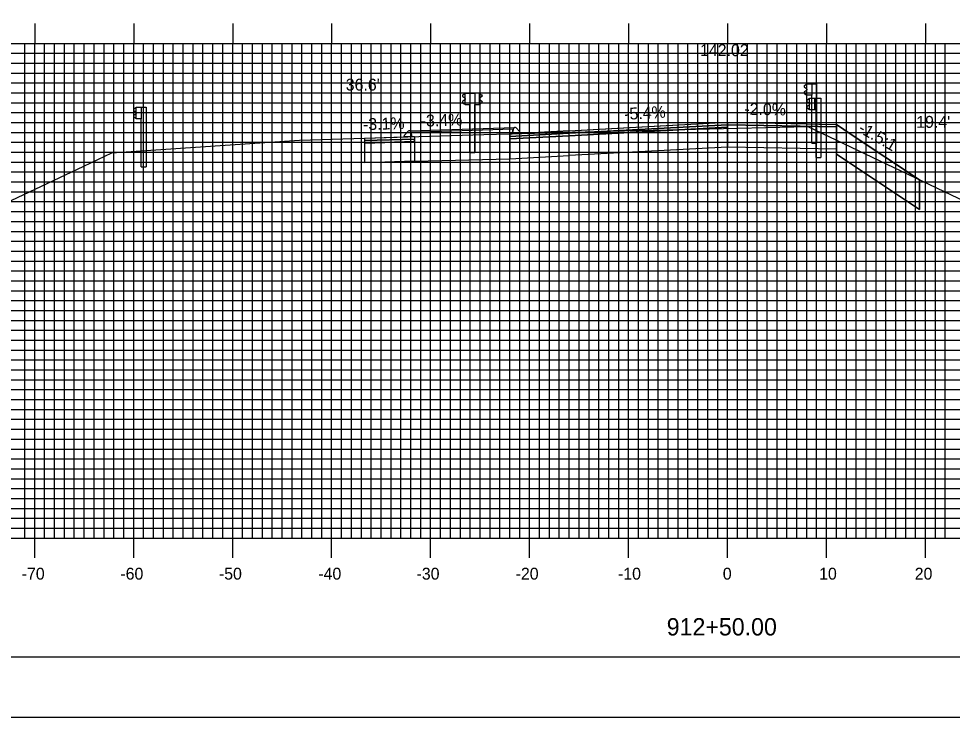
# Model space of a CAD drawing. Extents: x 860258 to 860601, y 364765 to 364985.
# Drawn here: x 860352.3 to 860446.6, y 364765.2 to 364835.8 of the extents above; entities that cross this region are included whole.
import ezdxf

# ---------------------------------------------------------------- set-up
doc = ezdxf.new("R2010")
doc.units = 0
for name, color, linetype in [('ANNOTATION', 7, 'Continuous'), ('BORDER', 7, 'Continuous'), ('D_Curb_Type_3M2_Lt', 7, 'Continuous'), ('D_Curb_Type_3M2_Rt', 7, 'Continuous'), ('D_Guardrail_Beam_Rt', 7, 'Continuous'), ('D_Roadway_Centerline', 7, 'Continuous'), ('D_Roadway_Centerline_Text', 7, 'Continuous'), ('D_Roadway_Edge_Shoulder', 7, 'Continuous'), ('D_Roadway_Edge_TW', 7, 'Continuous'), ('D_Roadway_FinishedGrade', 7, 'Continuous'), ('D_Roadway_Pavement', 7, 'Continuous'), ('D_Roadway_SubGrade', 7, 'Continuous'), ('D_Text_Standard', 7, 'Continuous'), ('H_V ANNOTATION', 7, 'Continuous'), ('M_Guardrail', 7, 'Continuous'), ('M_Roadway_Centerline', 7, 'Continuous'), ('MAJOR', 7, 'Continuous'), ('MINOR', 7, 'Continuous'), ('PATTERNING', 7, 'Continuous'), ('PLOT BOUNDARY', 7, 'Continuous'), ('S_Roadway_Centerline', 7, 'Continuous')]:
    doc.layers.add(name, color=color, linetype=linetype)

msp = doc.modelspace()

# ---------------------------------------------------------------- linework, layer by layer
at = {"layer": 'BORDER'}
msp.add_lwpolyline([(860274.299, 364771.302), (860594.299, 364771.302), (860594.299, 364981.302), (860274.299, 364981.302)], close=True, dxfattribs=at)
at = {"layer": 'D_Curb_Type_3M2_Lt'}
for p, q in [((860402.257, 364824.685), (860402.149, 364824.191)), ((860402.149, 364824.191), (860402.899, 364824.191)), ((860402.393, 364824.814), (860402.398, 364824.814)), ((860402.899, 364824.358), (860402.545, 364824.76)), ((860402.899, 364824.191), (860402.899, 364824.358))]:
    msp.add_line(p, q, dxfattribs=at)
msp.add_arc((860402.42, 364824.65), 0.167, 41.38705, 167.66476, dxfattribs=at)
at = {"layer": 'D_Curb_Type_3M2_Rt'}
for p, q in [((860391.259, 364824.017), (860391.613, 364824.419)), ((860391.901, 364824.344), (860392.009, 364823.85)), ((860391.259, 364823.85), (860391.259, 364824.017)), ((860392.009, 364823.85), (860391.259, 364823.85))]:
    msp.add_line(p, q, dxfattribs=at)
msp.add_arc((860391.738, 364824.309), 0.167, 12.33524, 138.61295, dxfattribs=at)
at = {"layer": 'D_Guardrail_Beam_Rt'}
for p, q in [((860432.08, 364827.644), (860431.937, 364827.544)), ((860431.937, 364827.401), (860432.132, 364827.265)), ((860432.132, 364827.066), (860431.937, 364826.93)), ((860432.17, 364827.665), (860432.096, 364827.651)), ((860432.166, 364827.2), (860432.166, 364827.13)), ((860432.17, 364827.749), (860432.858, 364827.749)), ((860432.17, 364826.582), (860432.17, 364827.749)), ((860432.691, 364827.749), (860432.691, 364826.582)), ((860432.795, 364827.749), (860432.795, 364826.582)), ((860432.858, 364827.749), (860433.329, 364827.749)), ((860432.858, 364827.749), (860432.858, 364826.582)), ((860433.329, 364827.749), (860433.329, 364821.749)), ((860431.937, 364826.786), (860432.08, 364826.686)), ((860432.096, 364826.68), (860432.17, 364826.665)), ((860432.858, 364826.582), (860432.17, 364826.582)), ((860432.837, 364821.749), (860432.837, 364826.582)), ((860432.837, 364821.749), (860433.329, 364821.749))]:
    msp.add_line(p, q, dxfattribs=at)
for centre, major_axis, start_param, end_param in [((860431.987, 364827.472), (-0.0877, 0), 5.323254, 7.243116), ((860431.987, 364826.858), (-0.0877, 0), 5.323254, 7.243116), ((860432.104, 364827.61), (-0.0417, 0), 4.907132, 5.323254), ((860432.087, 364827.2), (0.0789, 0), 0, 0.959931), ((860432.087, 364827.13), (0.0789, 0), 5.323254, 6.283185), ((860432.104, 364826.72), (-0.0417, 0), 0.959931, 1.376053)]:
    msp.add_ellipse(centre, major_axis=major_axis, ratio=0.995501, start_param=start_param, end_param=end_param, dxfattribs=at)
at = {"layer": 'D_Roadway_Centerline'}
for points in [[(860402.899, 364824.191), (860407.899, 364824.461), (860413.37, 364824.757), (860423.9, 364825.325), (860423.903, 364825.325), (860429.097, 364825.221), (860431.9, 364825.165), (860433.135, 364825.141), (860434.899, 364825.105), (860443.295, 364819.508)], [(860387.259, 364823.725), (860387.283, 364823.725), (860391.139, 364823.846), (860391.259, 364823.85)]]:
    msp.add_lwpolyline(points, dxfattribs=at)
at = {"layer": 'D_Roadway_Edge_Shoulder'}
for points in [[(860423.9, 364825.325), (860431.899, 364825.165), (860431.899, 364825.165), (860434.899, 364825.105), (860434.899, 364824.855), (860423.9, 364825.075)], [(860407.899, 364824.461), (860402.899, 364824.191), (860401.9, 364824.137), (860401.9, 364823.887), (860407.899, 364824.211)], [(860387.259, 364823.725), (860391.259, 364823.85), (860392.259, 364823.881), (860392.259, 364823.631), (860387.259, 364823.475)]]:
    msp.add_lwpolyline(points, close=True, dxfattribs=at)
at = {"layer": 'D_Roadway_Edge_TW'}
msp.add_lwpolyline([(860407.899, 364824.461), (860423.9, 364825.325), (860423.9, 364825.075), (860407.899, 364824.211)], close=True, dxfattribs=at)
at = {"layer": 'D_Roadway_FinishedGrade'}
msp.add_line((860434.899, 364825.105), (860434.899, 364822.105), dxfattribs=at)
for points in [[(860434.899, 364825.105), (860436.399, 364824.105), (860443.295, 364819.508)], [(860391.78, 364824.47), (860402.378, 364824.811)], [(860443.295, 364819.508), (860443.295, 364816.508), (860434.899, 364822.105)]]:
    msp.add_lwpolyline(points, dxfattribs=at)
at = {"layer": 'D_Roadway_Pavement'}
for points in [[(860407.899, 364824.211), (860423.9, 364825.075), (860423.9, 364824.825), (860407.899, 364823.961)], [(860407.899, 364824.211), (860401.9, 364823.887), (860401.9, 364823.637), (860407.899, 364823.961)], [(860387.259, 364823.475), (860392.259, 364823.631), (860392.259, 364823.381), (860387.259, 364823.225)]]:
    msp.add_lwpolyline(points, close=True, dxfattribs=at)
msp.add_lwpolyline([(860423.9, 364825.075), (860423.9, 364824.825)], dxfattribs=at)
msp.add_lwpolyline([(860423.9, 364825.075), (860423.9, 364824.825)], dxfattribs=at)
at = {"layer": 'D_Roadway_SubGrade'}
for points in [[(860423.9, 364824.825), (860423.9, 364825.075), (860434.899, 364824.855), (860434.899, 364825.105), (860434.899, 364822.605), (860423.9, 364822.825)], [(860392.259, 364823.881), (860392.259, 364821.381), (860401.9, 364821.637), (860401.9, 364823.637), (860401.9, 364823.887), (860401.9, 364824.137), (860402.14, 364824.15), (860402.247, 364824.64), (860391.909, 364824.307), (860392.004, 364823.874)], [(860407.899, 364823.961), (860423.9, 364824.825), (860423.9, 364822.825), (860407.899, 364821.961)], [(860387.259, 364823.225), (860392.259, 364823.381), (860392.259, 364823.631), (860392.259, 364821.381), (860387.259, 364821.225)], [(860407.899, 364823.961), (860401.9, 364823.637), (860401.9, 364823.887), (860401.9, 364821.637), (860407.899, 364821.961)]]:
    msp.add_lwpolyline(points, close=True, dxfattribs=at)
at = {"layer": 'M_Guardrail'}
for p, q in [((860431.808, 364829.124), (860431.665, 364829.024)), ((860431.665, 364828.881), (860431.86, 364828.745)), ((860431.907, 364829.146), (860431.825, 364829.131)), ((860431.907, 364829.219), (860432.396, 364829.219)), ((860431.907, 364828.052), (860431.907, 364829.219)), ((860432.396, 364829.219), (860432.888, 364829.219)), ((860432.396, 364829.219), (860432.396, 364828.052)), ((860432.888, 364829.219), (860432.888, 364823.219)), ((860397.286, 364828.176), (860397.143, 364828.076)), ((860397.143, 364827.933), (860397.338, 364827.797)), ((860397.385, 364828.197), (860397.303, 364828.183)), ((860397.385, 364828.27), (860397.874, 364828.27)), ((860397.385, 364827.104), (860397.385, 364828.27)), ((860397.862, 364828.273), (860397.862, 364822.273)), ((860398.354, 364828.273), (860397.862, 364828.273)), ((860397.874, 364828.27), (860398.366, 364828.27)), ((860397.874, 364828.27), (860397.874, 364827.104)), ((860398.843, 364828.273), (860398.354, 364828.273)), ((860398.354, 364828.273), (860398.354, 364827.106)), ((860398.366, 364828.27), (860398.366, 364822.27)), ((860398.843, 364827.106), (860398.843, 364828.273)), ((860398.843, 364828.2), (860398.926, 364828.185)), ((860399.086, 364827.935), (860398.89, 364827.799)), ((860398.942, 364828.178), (860399.086, 364828.078)), ((860431.86, 364828.525), (860431.665, 364828.389)), ((860431.665, 364828.246), (860431.808, 364828.146)), ((860431.825, 364828.139), (860431.907, 364828.125)), ((860431.894, 364828.681), (860431.894, 364828.59)), ((860432.396, 364828.052), (860431.907, 364828.052)), ((860432.396, 364823.219), (860432.396, 364828.052)), ((860397.338, 364827.577), (860397.143, 364827.441)), ((860397.143, 364827.298), (860397.286, 364827.198)), ((860397.303, 364827.191), (860397.385, 364827.177)), ((860397.372, 364827.733), (860397.372, 364827.642)), ((860397.874, 364827.104), (860397.385, 364827.104)), ((860397.874, 364822.27), (860397.874, 364827.104)), ((860398.354, 364822.273), (860398.354, 364827.106)), ((860398.354, 364827.106), (860398.843, 364827.106)), ((860398.926, 364827.193), (860398.843, 364827.179)), ((860398.857, 364827.735), (860398.857, 364827.644)), ((860398.89, 364827.579), (860399.086, 364827.443)), ((860399.086, 364827.3), (860398.942, 364827.2)), ((860364.066, 364826.743), (860363.922, 364826.643)), ((860363.922, 364826.5), (860364.117, 364826.364)), ((860364.117, 364826.144), (860363.922, 364826.008)), ((860364.164, 364826.765), (860364.082, 364826.75)), ((860364.151, 364826.3), (860364.151, 364826.209)), ((860364.164, 364826.837), (860364.654, 364826.837)), ((860364.164, 364825.671), (860364.164, 364826.837)), ((860364.654, 364826.837), (860365.145, 364826.837)), ((860364.654, 364826.837), (860364.654, 364825.671)), ((860365.145, 364826.837), (860365.145, 364820.837)), ((860363.922, 364825.865), (860364.066, 364825.765)), ((860364.082, 364825.758), (860364.164, 364825.744)), ((860364.654, 364825.671), (860364.164, 364825.671)), ((860364.654, 364820.837), (860364.654, 364825.671)), ((860432.396, 364823.219), (860432.888, 364823.219)), ((860398.354, 364822.273), (860397.862, 364822.273)), ((860397.874, 364822.27), (860398.366, 364822.27)), ((860364.654, 364820.837), (860365.145, 364820.837))]:
    msp.add_line(p, q, dxfattribs=at)
for centre, major_axis, start_param, end_param in [((860431.715, 364828.953), (-0.0877, 0), 5.323254, 7.243116), ((860431.832, 364829.09), (-0.0417, 0), 4.886922, 5.323254), ((860397.193, 364828.005), (-0.0877, 0), 5.323254, 7.243116), ((860397.31, 364828.142), (-0.0417, 0), 4.886922, 5.323254), ((860398.918, 364828.144), (0.0417, 0), 0.959931, 1.396263), ((860399.035, 364828.007), (0.0877, 0), 5.323254, 7.243116), ((860431.715, 364828.318), (-0.0877, 0), 5.323254, 7.243116), ((860431.832, 364828.18), (-0.0417, 0), 0.959931, 1.396263), ((860431.815, 364828.681), (0.0789, 0), 0, 0.959931), ((860431.815, 364828.59), (0.0789, 0), 5.323254, 6.283185), ((860397.193, 364827.369), (-0.0877, 0), 5.323254, 7.243116), ((860397.31, 364827.232), (-0.0417, 0), 0.959931, 1.396263), ((860397.293, 364827.733), (0.0789, 0), 0, 0.959931), ((860397.293, 364827.642), (0.0789, 0), 5.323254, 6.283185), ((860398.936, 364827.735), (-0.0789, 0), 5.323254, 6.283185), ((860398.936, 364827.644), (-0.0789, 0), 6.283185, 7.243116), ((860398.918, 364827.234), (0.0417, 0), 4.886922, 5.323254), ((860399.035, 364827.372), (0.0877, 0), 5.323254, 7.243116), ((860363.972, 364826.572), (-0.0877, 0), 5.323254, 7.243116), ((860363.972, 364825.937), (-0.0877, 0), 5.323254, 7.243116), ((860364.089, 364826.709), (-0.0417, 0), 4.886922, 5.323254), ((860364.072, 364826.3), (0.0789, 0), 0, 0.959931), ((860364.072, 364826.209), (0.0789, 0), 5.323254, 6.283185), ((860364.089, 364825.799), (-0.0417, 0), 0.959931, 1.396263)]:
    msp.add_ellipse(centre, major_axis=major_axis, ratio=0.995501, start_param=start_param, end_param=end_param, dxfattribs=at)
at = {"layer": 'MAJOR'}
for p, q in [((860353.899, 364835.306), (860353.899, 364833.302)), ((860363.899, 364835.306), (860363.899, 364833.302)), ((860373.899, 364835.306), (860373.899, 364833.302)), ((860383.899, 364835.306), (860383.899, 364833.302)), ((860393.899, 364835.306), (860393.899, 364833.302)), ((860403.899, 364835.306), (860403.899, 364833.302)), ((860413.899, 364835.306), (860413.899, 364833.302)), ((860423.899, 364835.306), (860423.899, 364833.302)), ((860433.899, 364835.306), (860433.899, 364833.302)), ((860443.899, 364835.306), (860443.899, 364833.302)), ((860283.899, 364833.302), (860563.899, 364833.302)), ((860283.899, 364833.302), (860563.899, 364833.302)), ((860353.899, 364783.302), (860353.899, 364833.302)), ((860363.899, 364783.302), (860363.899, 364833.302)), ((860373.899, 364783.302), (860373.899, 364833.302)), ((860383.899, 364783.302), (860383.899, 364833.302)), ((860393.899, 364783.302), (860393.899, 364833.302)), ((860403.899, 364783.302), (860403.899, 364833.302)), ((860413.899, 364783.302), (860413.899, 364833.302)), ((860423.899, 364783.302), (860423.899, 364833.302)), ((860433.899, 364783.302), (860433.899, 364833.302)), ((860443.899, 364783.302), (860443.899, 364833.302)), ((860283.899, 364828.302), (860563.899, 364828.302)), ((860283.899, 364823.302), (860563.899, 364823.302)), ((860283.899, 364818.302), (860563.899, 364818.302)), ((860283.899, 364813.302), (860563.899, 364813.302)), ((860283.899, 364808.302), (860563.899, 364808.302)), ((860283.899, 364803.302), (860563.899, 364803.302)), ((860283.899, 364798.302), (860563.899, 364798.302)), ((860283.899, 364793.302), (860563.899, 364793.302)), ((860283.899, 364788.302), (860563.899, 364788.302)), ((860283.899, 364783.302), (860563.899, 364783.302)), ((860283.899, 364783.302), (860563.899, 364783.302)), ((860353.899, 364781.298), (860353.899, 364783.302)), ((860363.899, 364781.298), (860363.899, 364783.302)), ((860373.899, 364781.298), (860373.899, 364783.302)), ((860383.899, 364781.298), (860383.899, 364783.302)), ((860393.899, 364781.298), (860393.899, 364783.302)), ((860403.899, 364781.298), (860403.899, 364783.302)), ((860413.899, 364781.298), (860413.899, 364783.302)), ((860423.899, 364781.298), (860423.899, 364783.302)), ((860433.899, 364781.298), (860433.899, 364783.302)), ((860443.899, 364781.298), (860443.899, 364783.302))]:
    msp.add_line(p, q, dxfattribs=at)
at = {"layer": 'MINOR'}
for p, q in [((860352.899, 364783.302), (860352.899, 364833.302)), ((860354.899, 364783.302), (860354.899, 364833.302)), ((860355.899, 364783.302), (860355.899, 364833.302)), ((860356.899, 364783.302), (860356.899, 364833.302)), ((860357.899, 364783.302), (860357.899, 364833.302)), ((860358.899, 364783.302), (860358.899, 364833.302)), ((860359.899, 364783.302), (860359.899, 364833.302)), ((860360.899, 364783.302), (860360.899, 364833.302)), ((860361.899, 364783.302), (860361.899, 364833.302)), ((860362.899, 364783.302), (860362.899, 364833.302)), ((860364.899, 364783.302), (860364.899, 364833.302)), ((860365.899, 364783.302), (860365.899, 364833.302)), ((860366.899, 364783.302), (860366.899, 364833.302)), ((860367.899, 364783.302), (860367.899, 364833.302)), ((860368.899, 364783.302), (860368.899, 364833.302)), ((860369.899, 364783.302), (860369.899, 364833.302)), ((860370.899, 364783.302), (860370.899, 364833.302)), ((860371.899, 364783.302), (860371.899, 364833.302)), ((860372.899, 364783.302), (860372.899, 364833.302)), ((860374.899, 364783.302), (860374.899, 364833.302)), ((860375.899, 364783.302), (860375.899, 364833.302)), ((860376.899, 364783.302), (860376.899, 364833.302)), ((860377.899, 364783.302), (860377.899, 364833.302)), ((860378.899, 364783.302), (860378.899, 364833.302)), ((860379.899, 364783.302), (860379.899, 364833.302)), ((860380.899, 364783.302), (860380.899, 364833.302)), ((860381.899, 364783.302), (860381.899, 364833.302)), ((860382.899, 364783.302), (860382.899, 364833.302)), ((860384.899, 364783.302), (860384.899, 364833.302)), ((860385.899, 364783.302), (860385.899, 364833.302)), ((860386.899, 364783.302), (860386.899, 364833.302)), ((860387.899, 364783.302), (860387.899, 364833.302)), ((860388.899, 364783.302), (860388.899, 364833.302)), ((860389.899, 364783.302), (860389.899, 364833.302)), ((860390.899, 364783.302), (860390.899, 364833.302)), ((860391.899, 364783.302), (860391.899, 364833.302)), ((860392.899, 364783.302), (860392.899, 364833.302)), ((860394.899, 364783.302), (860394.899, 364833.302)), ((860395.899, 364783.302), (860395.899, 364833.302)), ((860396.899, 364783.302), (860396.899, 364833.302)), ((860397.899, 364783.302), (860397.899, 364833.302)), ((860398.899, 364783.302), (860398.899, 364833.302)), ((860399.899, 364783.302), (860399.899, 364833.302)), ((860400.899, 364783.302), (860400.899, 364833.302)), ((860401.899, 364783.302), (860401.899, 364833.302)), ((860402.899, 364783.302), (860402.899, 364833.302)), ((860404.899, 364783.302), (860404.899, 364833.302)), ((860405.899, 364783.302), (860405.899, 364833.302)), ((860406.899, 364783.302), (860406.899, 364833.302)), ((860407.899, 364783.302), (860407.899, 364833.302)), ((860408.899, 364783.302), (860408.899, 364833.302)), ((860409.899, 364783.302), (860409.899, 364833.302)), ((860410.899, 364783.302), (860410.899, 364833.302)), ((860411.899, 364783.302), (860411.899, 364833.302)), ((860412.899, 364783.302), (860412.899, 364833.302)), ((860414.899, 364783.302), (860414.899, 364833.302)), ((860415.899, 364783.302), (860415.899, 364833.302)), ((860416.899, 364783.302), (860416.899, 364833.302)), ((860417.899, 364783.302), (860417.899, 364833.302)), ((860418.899, 364783.302), (860418.899, 364833.302)), ((860419.899, 364783.302), (860419.899, 364833.302)), ((860420.899, 364783.302), (860420.899, 364833.302)), ((860421.899, 364783.302), (860421.899, 364833.302)), ((860422.899, 364783.302), (860422.899, 364833.302)), ((860424.899, 364783.302), (860424.899, 364833.302)), ((860425.899, 364783.302), (860425.899, 364833.302)), ((860426.899, 364783.302), (860426.899, 364833.302)), ((860427.899, 364783.302), (860427.899, 364833.302)), ((860428.899, 364783.302), (860428.899, 364833.302)), ((860429.899, 364783.302), (860429.899, 364833.302)), ((860430.899, 364783.302), (860430.899, 364833.302)), ((860431.899, 364783.302), (860431.899, 364833.302)), ((860432.899, 364783.302), (860432.899, 364833.302)), ((860434.899, 364783.302), (860434.899, 364833.302)), ((860435.899, 364783.302), (860435.899, 364833.302)), ((860436.899, 364783.302), (860436.899, 364833.302)), ((860437.899, 364783.302), (860437.899, 364833.302)), ((860438.899, 364783.302), (860438.899, 364833.302)), ((860439.899, 364783.302), (860439.899, 364833.302)), ((860440.899, 364783.302), (860440.899, 364833.302)), ((860441.899, 364783.302), (860441.899, 364833.302)), ((860442.899, 364783.302), (860442.899, 364833.302)), ((860444.899, 364783.302), (860444.899, 364833.302)), ((860445.899, 364783.302), (860445.899, 364833.302)), ((860283.899, 364832.302), (860563.899, 364832.302)), ((860283.899, 364831.302), (860563.899, 364831.302)), ((860283.899, 364830.302), (860563.899, 364830.302)), ((860283.899, 364829.302), (860563.899, 364829.302)), ((860283.899, 364827.302), (860563.899, 364827.302)), ((860283.899, 364826.302), (860563.899, 364826.302)), ((860283.899, 364825.302), (860563.899, 364825.302)), ((860283.899, 364824.302), (860563.899, 364824.302)), ((860283.899, 364822.302), (860563.899, 364822.302)), ((860283.899, 364821.302), (860563.899, 364821.302)), ((860283.899, 364820.302), (860563.899, 364820.302)), ((860283.899, 364819.302), (860563.899, 364819.302)), ((860283.899, 364817.302), (860563.899, 364817.302)), ((860283.899, 364816.302), (860563.899, 364816.302)), ((860283.899, 364815.302), (860563.899, 364815.302)), ((860283.899, 364814.302), (860563.899, 364814.302)), ((860283.899, 364812.302), (860563.899, 364812.302)), ((860283.899, 364811.302), (860563.899, 364811.302)), ((860283.899, 364810.302), (860563.899, 364810.302)), ((860283.899, 364809.302), (860563.899, 364809.302)), ((860283.899, 364807.302), (860563.899, 364807.302)), ((860283.899, 364806.302), (860563.899, 364806.302)), ((860283.899, 364805.302), (860563.899, 364805.302)), ((860283.899, 364804.302), (860563.899, 364804.302)), ((860283.899, 364802.302), (860563.899, 364802.302)), ((860283.899, 364801.302), (860563.899, 364801.302)), ((860283.899, 364800.302), (860563.899, 364800.302)), ((860283.899, 364799.302), (860563.899, 364799.302)), ((860283.899, 364797.302), (860563.899, 364797.302)), ((860283.899, 364796.302), (860563.899, 364796.302)), ((860283.899, 364795.302), (860563.899, 364795.302)), ((860283.899, 364794.302), (860563.899, 364794.302)), ((860283.899, 364792.302), (860563.899, 364792.302)), ((860283.899, 364791.302), (860563.899, 364791.302)), ((860283.899, 364790.302), (860563.899, 364790.302)), ((860283.899, 364789.302), (860563.899, 364789.302)), ((860283.899, 364787.302), (860563.899, 364787.302)), ((860283.899, 364786.302), (860563.899, 364786.302)), ((860283.899, 364785.302), (860563.899, 364785.302)), ((860283.899, 364784.302), (860563.899, 364784.302))]:
    msp.add_line(p, q, dxfattribs=at)
at = {"layer": 'PATTERNING'}
for points in [[(860443.295, 364819.508), (860436.399, 364824.105), (860434.899, 364825.105)], [(860434.899, 364825.105), (860434.899, 364822.605), (860434.899, 364822.105)], [(860434.899, 364822.105), (860443.295, 364816.508), (860443.295, 364819.508)]]:
    msp.add_lwpolyline(points, dxfattribs=at)
at = {"layer": 'PLOT BOUNDARY'}
msp.add_lwpolyline([(860258.113, 364765.184), (860598.113, 364765.184), (860598.113, 364985.184), (860258.113, 364985.184)], close=True, dxfattribs=at)
at = {"layer": 'S_Roadway_Centerline'}
msp.add_lwpolyline([(860283.899, 364796.963), (860290.184, 364796.965), (860299.748, 364797.982), (860305.932, 364798.532), (860313.615, 364801.218), (860322.257, 364803.596), (860358.848, 364820.882), (860361.695, 364822.243), (860363.152, 364822.341), (860380.657, 364823.518), (860399.268, 364824.101), (860412.087, 364824.442), (860420.65, 364824.626), (860432, 364824.886), (860461.596, 364810.794)], dxfattribs=at)

# ---------------------------------------------------------------- texts
at = {"layer": 'ANNOTATION'}
for s, rotation, p in [('-5.4%', 3.09085, (860413.484, 364825.566)), ('-2.0%', 358.85406, (860425.587, 364826.092)), ('-3.4%', 1.95444, (860392.92, 364824.871)), ('-3.1%', 1.79997, (860387.084, 364824.52)), ('-1.5:1', 330.177, (860437.009, 364824.396))]:
    msp.add_text(s, height=1.2, rotation=rotation, dxfattribs=at).set_placement(p)
at = {"layer": 'D_Roadway_Centerline_Text'}
msp.add_text('142.02', height=1.2, dxfattribs=at).set_placement((860421.122, 364832.011))
at = {"layer": 'D_Text_Standard'}
for s, p in [("36.6'", (860385.324, 364828.529)), ("19.4'", (860442.964, 364824.764))]:
    msp.add_text(s, height=1.2, dxfattribs=at).set_placement(p)
at = {"layer": 'H_V ANNOTATION'}
for s, height, p in [('-70', 1.2, (860352.583, 364779.102)), ('-60', 1.2, (860362.551, 364779.102)), ('-50', 1.2, (860372.508, 364779.102)), ('-40', 1.2, (860382.551, 364779.102)), ('-30', 1.2, (860392.476, 364779.102)), ('-20', 1.2, (860402.486, 364779.102)), ('-10', 1.2, (860412.829, 364779.102)), ('0', 1.2, (860423.417, 364779.102)), ('10', 1.2, (860433.15, 364779.102)), ('20', 1.2, (860442.807, 364779.102)), ('912+50.00', 1.75, (860417.751, 364773.458))]:
    msp.add_text(s, height=height, dxfattribs=at).set_placement(p)
at = {"layer": 'M_Roadway_Centerline'}
for s, p in [('C', (860412.082, 364824.442)), ('L', (860412.087, 364824.435)), ('C', (860380.652, 364823.518)), ('L', (860380.657, 364823.511))]:
    msp.add_text(s, height=0.0146, dxfattribs=at).set_placement(p)

doc.saveas('drawing.dxf')
